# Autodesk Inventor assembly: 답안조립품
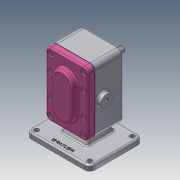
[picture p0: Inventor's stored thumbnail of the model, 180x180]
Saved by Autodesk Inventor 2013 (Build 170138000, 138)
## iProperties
Created: 2020-04
Part Number: 답안조립품
Document SubType Name: Assembly
Designer: user
Author: user
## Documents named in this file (11)
- C:\Users\user\Desktop\700407V1056\답안조립품.iam
- C:\Users\user\Desktop\700407V1056\본체.ipt
- C:\Users\user\Desktop\700407V1056\Ű 6 x 6 x 18.ipt
- C:\Users\user\Desktop\700407V1056\개스킷.ipt
- C:\Users\user\Desktop\700407V1056\메인축.ipt
- C:\Users\user\Desktop\700407V1056\베어링부시.ipt
- C:\Users\user\Desktop\700407V1056\볼트 M5.ipt
- C:\Users\user\Desktop\700407V1056\서브축.ipt
- C:\Users\user\Desktop\700407V1056\스퍼기어.ipt
- C:\Users\user\Desktop\700407V1056\오일 실 16 28 7.ipt
- C:\Users\user\Desktop\700407V1056\커버.ipt
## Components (3 placed, 2 different names)
1. Ű 6 x 6 x 18:1
2. 개스킷:1
3. Ű 6 x 6 x 18:2
